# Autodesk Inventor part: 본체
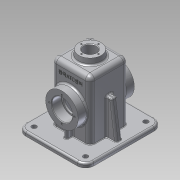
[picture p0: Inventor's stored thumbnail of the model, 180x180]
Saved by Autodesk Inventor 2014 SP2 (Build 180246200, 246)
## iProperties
Created: 2016-08
Part Number: 본체
Material: 알루미늄 6061
Document SubType Name: Modeling
Designer: user
Density: 2.71 g/cm^3
Appearance: 알루미늄 - 평지
Mass: 796.093 g
Surface Area: 911.214 cm^2
Volume: 293.761 cm^3
Author: user
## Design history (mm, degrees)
sketch "스케치2"
  geometry: L1 (-52.5, -60)-(52.5, -60); L2 (52.5, -60)-(52.5, 60); L3 (52.5, 60)-(-52.5, 60); L4 (-52.5, 60)-(-52.5, -60); L5 (-52.5, -60)-(52.5, 60); L6 (52.5, -60)-(-52.5, 60); 3 further points
  constraints: 12 end point, 3 midpoint, 2 parallel, 1 coincident, 1 horizontal, 1 perpendicular
  dimensions: "d4" = 120 distance of L3.end L1.start; "d5" = 105 distance of L2.end L3.end
extrude "돌출2" new body sketch "스케치2" distance "d6" = 3; taper "d7" = 0 deg
sketch "스케치3" dims "d105" = 3
  geometry: L1 (-57.5, 65)-(57.5, 65); L2 (57.5, 65)-(57.5, -65); L3 (57.5, -65)-(-57.5, -65); L4 (-57.5, -65)-(-57.5, 65); L5 (-57.5, 65)-(57.5, -65); L6 (57.5, 65)-(-57.5, -65); 3 further points
  constraints: 12 end point, 3 midpoint, 2 parallel, 1 coincident, 1 horizontal, 1 perpendicular
  dimensions: "d8" = 115 distance of L1.start L1.end; "d9" = 130 distance of L1.end L2.end
extrude "돌출3" join sketch "스케치3" distance "d10" = 7; taper "d11" = 0 deg
sketch "스케치4"
  geometry: L1 (32.5, 32.5)-(-32.5, 32.5); L2 (-32.5, 32.5)-(-32.5, -32.5); L3 (-32.5, -32.5)-(32.5, -32.5); L4 (32.5, -32.5)-(32.5, 32.5); L5 (32.5, 32.5)-(-32.5, -32.5); L6 (-32.5, 32.5)-(32.5, -32.5); 3 further points
  constraints: 12 end point, 3 midpoint, 2 parallel, 2 perpendicular, 1 coincident, 1 horizontal
  dimensions: "d12" = 65 distance of L3.end L1.start
extrude "돌출4" join sketch "스케치4" distance "d13" = 100; taper "d14" = 0 deg
fillet "모깎기1" dims "d15" = 8
fillet "모깎기2" dims "d16" = 8
feature "쉘1" dims "d17" = 5
sketch "스케치5"
  geometry: L1 (95, 0)-(0, 0) reference; L2 (95, 110)-(95, 0) reference; L3 (0, 110)-(95, 110) reference; L4 (0, 0)-(0, 110) reference; L5 (20, 79.5)-(20, 30.5) reference; L6 (72, 82.5)-(23, 82.5) reference; L7 (75, 30.5)-(75, 79.5) reference; L8 (23, 27.5)-(72, 27.5) reference; A1 r 3 centre (23, 79.5) between (23, 82.5) and (20, 79.5) reference; A2 r 3 centre (72, 79.5) between (75, 79.5) and (72, 82.5) reference; A3 r 3 centre (72, 30.5) between (72, 27.5) and (75, 30.5) reference; A4 r 3 centre (23, 30.5) between (20, 30.5) and (23, 27.5) reference; 1 further point
extrude "돌출5" join sketch "스케치5" stored distance "d18" = 100; taper "d19" = 0 deg
sketch "스케치6"
  geometry: L1 (77, 10)-(-28, 10) reference; C1 r 27.5 at (24.5, -45); 2 further points
  constraints: 1 centre point, 1 midpoint, 1 vertical alignment
  dimensions: "d20" = 55 diameter of C1; "d21" = 55 distance from line of L1 C1.centre
extrude "돌출6" join sketch "스케치6" distance "d22" = 15; taper "d23" = 0 deg
sketch "스케치7"
  geometry: C1 r 20 at (0, 0); 1 further point
  constraints: 1 centre point, 1 coincident
  dimensions: "d24" = 40 diameter of C1
extrude "돌출7" join sketch "스케치7" distance "d25" = 10; taper "d26" = -7 deg
sketch "스케치8"
  geometry: L1 (47.5, 55)-(47.5, 72.5); L2 (47.5, 72.5)-(30.5, 72.5); L3 (30.5, 72.5)-(30.5, 70); L4 (30.5, 70)-(-30.5, 70); L5 (-30.5, 70)-(-30.5, 72.5); L6 (-30.5, 72.5)-(-47.5, 72.5); L7 (-47.5, 72.5)-(-47.5, 55); L8 (-47.5, 55)-(47.5, 55); L9 (47.5, 27.5)-(47.5, 82.5) reference; L10 (-47.5, 27.5)-(-47.5, 82.5) reference; 1 further point
  constraints: 16 end point, 4 collinear, 4 parallel, 2 vertical, 1 perpendicular
  dimensions: "d27" = 17 distance of L1.end L2.end; "d28" = 35 diameter of L2 L8; "d29" = 30 diameter of L4 L8; "d30" = 55 vertical distance of point (0, 0) L1.start; "d31" = 35 diameter of L6 L8
revolve "회전1" sketch "스케치8" stored, may be unused: angle "d32" = 90 deg
hole "구멍1" diameter "d35" = 21; stored, may be unused: countersink angle "d39" = 90 deg, drill point angle "d41" = 0 deg; dims "d33" = 10, "d34" = 10, "d36" = 6, "d37" = 4, "d38" = 2, "d40" = 43.25
sketch "스케치9"
  geometry: L1 (-32.5, 102)-(-32.5, 10) reference; L2 (-57.5, 10)-(57.5, 10) reference; L3 (-49.5, 10)-(-41.068, 70); L4 (-57.5, 3)-(-57.5, 10) reference; L5 (-41.068, 70)-(-32.5, 70); L6 (52.5, 0)-(-52.5, 0) reference; 1 further point
  constraints: 4 end point, 2 point on line, 1 perpendicular
  dimensions: "d42" = 8 distance of L2.start L3.start; "d43" = 8 deg angle of L4 L3; "d130" = 70 distance between parallel lines of L6 L5
feature "리브1" sketch "스케치9" dims "d45" = 1, "d46" = 10, "d47" = 0, "d48" = 0, "d49" = 1, "d50" = 1
fillet "모깎기3" dims "d51" = 9
hole "구멍2" diameter "d54" = 8; stored, may be unused: countersink angle "d58" = 90 deg, drill point angle "d60" = 0 deg; dims "d52" = 10, "d53" = 10, "d55" = 6, "d56" = 4, "d57" = 2, "d59" = 8
sketch "스케치11" dims "d67" = 42
  geometry: C1 r 27.5 at (0, 0) reference; 3 further points
  constraints: 2 vertical alignment, 1 coincident, 2 other
hole "구멍3" sketch "스케치11" at (0, -21) diameter "d68" = 3.242; stored, may be unused: countersink angle "d72" = 90 deg, drill point angle "d74" = 118 deg; dims "d69" = 8, "d70" = 4, "d71" = 2, "d73" = 10
sketch "스케치12" dims "d75" = 42
  geometry: C1 r 27.5 at (0, 0) reference; 3 further points
  constraints: 2 vertical alignment, 1 coincident, 2 other
hole "구멍4" sketch "스케치12" at (0, 21) diameter "d76" = 3.242; stored, may be unused: countersink angle "d80" = 90 deg, drill point angle "d82" = 118 deg; dims "d77" = 8, "d78" = 4, "d79" = 2, "d81" = 10
sketch "스케치13" dims "d89" = 29
  geometry: 3 further points
  constraints: 2 vertical alignment, 1 coincident, 2 other
hole "구멍5" sketch "스케치13" at (0, 14.5) diameter "d90" = 2.459; stored, may be unused: countersink angle "d94" = 90 deg, drill point angle "d96" = 118 deg; dims "d91" = 7, "d92" = 4, "d93" = 2, "d95" = 9
sketch "스케치14"
  geometry: L1 (-8, 0)-(-8, -92) reference; L2 (5.728, 18)-(43.272, 18) reference; 2 further points
  constraints: 1 other
  dimensions: "d100" = 32.5 distance from line of L1 point (24.5, -8); "d101" = 26 distance from line of L2 point (24.5, -8)
feature "엠보싱1" sketch "스케치14" dims "d102" = 0.5, "d103" = 0
fillet "모깎기4" dims "d104" = 14
fillet "모깎기5" dims "d105" = 3
fillet "모깎기6" dims "d106" = 3
fillet "모깎기7" dims "d107" = 3
fillet "모깎기8" dims "d108" = 3
fillet "모깎기9" dims "d109" = 3
fillet "모깎기11" dims "d111" = 3
chamfer "모따기1" distance "d113" = 1; stored, may be unused: second distance "d114" = 2, angle "d115" = 45 deg
sketch "스케치15"
  geometry: L1 (-47.5, 27.5)-(-32.5, 27.5) reference; L2 (-32.5, 10)-(-32.5, 42.51) reference; L3 (-51, 10)-(51, 10) reference; L4 (-42.5, 27.5)-(-42.5, 10); L5 (-27.5, 102)-(-27.5, 0) reference; 1 further point
  constraints: 2 end point, 2 point on line, 1 perpendicular
  dimensions: "d116" = 15 distance between parallel lines of L5 L4
feature "리브2" sketch "스케치15" dims "d117" = 1, "d118" = 6, "d119" = 0, "d120" = 0, "d121" = 1, "d122" = 1
fillet "모깎기13" dims "d123" = 3
fillet "모깎기14" dims "d124" = 3
fillet "모깎기15" dims "d125" = 1
chamfer "모따기2" distance "d126" = 1; stored, may be unused: second distance "d127" = 2, angle "d128" = 45 deg
fillet "모깎기16" dims "d129" = 0.3
node "솔리드2"
mirror "대칭1"
mirror "대칭2"
pattern_linear "직사각형 패턴1" dims "d63" = 102, "d66" = 87
pattern_circular "원형 패턴1" dims angle "d84" = 360 deg
pattern_circular "원형 패턴2" dims angle "d87" = 360 deg
pattern_circular "원형 패턴3" dims angle "d98" = 360 deg
mirror "대칭3"
node "투영된 루프1"
